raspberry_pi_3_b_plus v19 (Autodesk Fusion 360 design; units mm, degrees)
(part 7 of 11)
sketch "Sketch2" plane through (0, 0, 5.17) normal (0, 0, 1) x axis (-1, 0.0001, 0)
  line L1 (4.3404, -3.1995) -> (4.3405, -3.7995)
  line L2 (3.4404, -3.1996) -> (4.3404, -3.1995)
  line L3 (3.4405, -3.7996) -> (3.4404, -3.1996)
  line L4 (4.3405, -3.7995) -> (3.4405, -3.7996)
  line L5 (4.9405, -3.7994) -> (4.9404, -3.1994)
  line L6 (2.7854, -4.1591) -> (2.7354, -4.1591)
  line L7 (3.9604, -4.0652) -> (3.9604, -4.1092)
  line L8 (2.1854, -4.1591) -> (1.4604, -4.1591)
  line L9 (2.9747, -4.2244) -> (2.8668, -4.1763)
  line L10 (3.8604, -4.2092) -> (3.5269, -4.2092)
  line L11 (3.4504, -4.2244) -> (2.9747, -4.2244)
  line L12 (1.4604, -4.1591) -> (1.4604, -2.8397)
  line L13 (4.9404, -3.4994) -> (1.4604, -3.4994)
  line L14 (4.3405, -3.7995) -> (3.4405, -3.7996)
  line L15 (2.1854, -2.8397) -> (1.4604, -2.8397)
  line L16 (2.7854, -2.8397) -> (2.7354, -2.8397)
  line L17 (2.9747, -2.7744) -> (2.8668, -2.8224)
  line L18 (3.4504, -2.7744) -> (2.9747, -2.7744)
  line L19 (3.8604, -2.7896) -> (3.5269, -2.7896)
  line L20 (3.9604, -2.9336) -> (3.9604, -2.8896)
  line L21 (1.3604, -4.1323) -> (1.0901, -3.9762)
  line L22 (1.4604, -4.1591) -> (1.4604, -4.1591)
  line L23 (-2.17, -3.9494) -> (0.9901, -3.9494)
  line L24 (1.3604, -2.8665) -> (1.0901, -3.0226)
  line L25 (0.9901, -3.9494) -> (0.9901, -3.0494)
  line L26 (3.4405, -3.7996) -> (3.4404, -3.1996)
  line L27 (0.9604, -4.1591) -> (1.4604, -4.1591)
  line L28 (0.9604, -2.8353) -> (0.9604, -4.1591)
  line L29 (1.4604, -2.8397) -> (0.9604, -2.8353)
  arc A1 centre (3.5269, -4.4092) radius 0.2 clockwise from (3.4504, -4.2244) to (3.5269, -4.2092)
  arc A2 centre (4.2264, -3.6495) radius 0.15 clockwise from (4.2264, -3.7995) to (4.1434, -3.7744)
  arc A3 centre (4.0604, -3.8994) radius 0.15 clockwise from (3.9354, -3.9823) to (4.1434, -3.7744)
  arc A4 centre (3.8104, -4.0652) radius 0.15 clockwise from (3.9354, -3.9823) to (3.9604, -4.0652)
  arc A5 centre (3.8604, -4.1092) radius 0.1 clockwise from (3.9604, -4.1092) to (3.8604, -4.2092)
  arc A6 centre (2.7854, -4.3591) radius 0.2 clockwise from (2.7854, -4.1591) to (2.8668, -4.1763)
  arc A7 centre (2.7354, -4.3591) radius 0.2 clockwise from (2.5979, -4.2138) to (2.7354, -4.1591)
  arc A8 centre (2.4604, -4.0686) radius 0.2 clockwise from (2.5979, -4.2138) to (2.3229, -4.2138)
  arc A9 centre (2.1854, -4.3591) radius 0.2 clockwise from (2.1854, -4.1591) to (2.3229, -4.2138)
  arc A10 centre (2.1854, -2.6397) radius 0.2 clockwise from (2.3229, -2.785) to (2.1854, -2.8397)
  arc A11 centre (2.7354, -2.6397) radius 0.2 clockwise from (2.7354, -2.8397) to (2.5979, -2.785)
  arc A12 centre (2.7854, -2.6397) radius 0.2 clockwise from (2.8668, -2.8224) to (2.7854, -2.8397)
  arc A13 centre (3.5269, -2.5896) radius 0.2 clockwise from (3.5269, -2.7896) to (3.4504, -2.7744)
  arc A14 centre (3.8604, -2.8896) radius 0.1 clockwise from (3.8604, -2.7896) to (3.9604, -2.8896)
  arc A15 centre (3.8104, -2.9336) radius 0.15 clockwise from (3.9604, -2.9336) to (3.9354, -3.0165)
  arc A16 centre (4.0604, -3.0994) radius 0.15 clockwise from (4.1434, -3.2244) to (3.9354, -3.0165)
  arc A17 centre (4.2264, -3.3493) radius 0.15 clockwise from (4.1434, -3.2244) to (4.2264, -3.1993)
  arc A18 centre (2.4604, -2.9302) radius 0.2 clockwise from (2.3229, -2.785) to (2.5979, -2.785)
  arc A19 centre (1.4604, -3.9591) radius 0.2 clockwise from (1.4604, -4.1591) to (1.3604, -4.1323)
  arc A20 centre (0.9901, -4.1494) radius 0.2 clockwise from (0.9901, -3.9494) to (1.0901, -3.9762)
  arc A21 centre (0.9901, -2.8494) radius 0.2 clockwise from (1.0901, -3.0226) to (0.9901, -3.0494)
  arc A22 centre (1.4604, -3.0397) radius 0.2 clockwise from (1.3604, -2.8665) to (1.4604, -2.8397)
  point P32 (2.7604, -4.1591)
  point P35 (1.4604, -3.4994)
  point P33 (2.3229, -4.2138)
  point P37 (2.3229, -4.2138)
  point P36 (4.9404, -3.4994)
  point P22 (1.4604, -4.1591)
  point P38 (1.4604, -4.1591)
  point P9 (4.1434, -3.7744)
  point P62 (4.1434, -3.2244)
  point P10 (3.9604, -4.1092)
  point P57 (3.9604, -2.8896)
  point P12 (3.4504, -4.2244)
  point P52 (3.4504, -2.7744)
  point P13 (3.5269, -4.2092)
  point P54 (3.5269, -2.7896)
  point P14 (2.8668, -4.1763)
  point P50 (2.8668, -2.8224)
  point P16 (3.8604, -4.2092)
  point P55 (3.8604, -2.7896)
  point P17 (3.9354, -3.9823)
  point P60 (3.9354, -3.0165)
  point P18 (2.9747, -4.2244)
  point P51 (2.9747, -2.7744)
  point P19 (3.9604, -4.0652)
  point P58 (3.9604, -2.9336)
  point P20 (2.7854, -4.1591)
  point P48 (2.7854, -2.8397)
  point P21 (2.7354, -4.1591)
  point P46 (2.7354, -2.8397)
  point P41 (1.4604, -2.8397)
  point P23 (2.1854, -4.1591)
  point P42 (2.1854, -2.8397)
  point P29 (2.5979, -4.2138)
  point P47 (2.5979, -2.785)
  point P44 (2.3229, -2.785)
  point P66 (2.3229, -2.785)
  point P8 (1.4604, -2.8397)
  point P78 (1.4604, -2.8397)
  point P67 (1.3604, -4.1323)
  point P76 (1.3604, -2.8665)
  point P69 (0.9901, -3.9494)
  point P75 (0.9901, -3.0494)
  point P71 (1.0901, -3.9762)
  point P74 (1.0901, -3.0226)
  point P11 (4.2264, -3.7995)
  point P25 (4.0604, -3.8994)
  point P31 (2.4604, -4.0686)
  point P80 (0.9604, -4.1591)
  horizontal L8
  horizontal L11
  horizontal L10
  vertical L7
  vertical L12
  tangent A2 A3
  tangent A3 A4
  tangent L7 A4
  tangent L7 A5
  tangent A1 L10
  tangent L10 A5
  horizontal L6
  tangent L9 A6
  tangent L6 A6
  tangent L6 A7
  tangent A7 A8
  midpoint L6 P32
  tangent L8 A9
  collinear L6 L8
  midpoint L12 P35
  horizontal L13
  coincident P33 P37
  tangent A8 A9
  midpoint L5 P36
  tangent L4 A2
  coincident P22 P38
  symmetric P9 L13 P62
  symmetric P10 L13 P57
  symmetric P12 L13 P52
  symmetric P13 L13 P54
  symmetric P14 L13 P50
  symmetric P16 L13 P55
  symmetric P17 L13 P60
  symmetric P18 L13 P51
  symmetric P19 L13 P58
  symmetric P20 L13 P48
  symmetric P21 L13 P46
  symmetric P22 L13 P41
  symmetric P23 L13 P42
  symmetric A1 L13 A13
  symmetric A2 L13 A17
  symmetric A3 L13 A16
  symmetric A4 L13 A15
  symmetric A5 L13 A14
  symmetric A6 L13 A12
  symmetric P29 L13 P47
  symmetric A7 L13 A11
  symmetric A8 L13 A18
  symmetric P33 L13 P44
  symmetric A9 L13 A10
  symmetric L13 P37 P66
  coincident P8 P41
  perpendicular L12 L22
  tangent L8 A19
  horizontal L23
  tangent L21 A19
  tangent L21 A20
  equal A19 A20
  tangent L23 A20
  symmetric P22 L13 P78
  symmetric L13 P67 P76
  symmetric L13 A19 A22
  symmetric L13 P69 P75
  symmetric L13 P71 P74
  symmetric L13 A20 A21
  horizontal L27
  perpendicular L27 L28
  coincident L4 P11
  dimension "d304_1_1" = 0.15
  dimension "d305_1_1" radius A3 = 0.15
  dimension "d306_1_1" radius A4 = 0.15
  dimension "d307_1_1" radius A5 = 0.1
  dimension "d308_1_1" radius A1 = 0.2
  dimension "d309_1_1" angle L9 L11 = 24
  dimension "d310_1_1" distance L7 P32 = 1.2
  dimension "d311_1_1" radius A6 = 0.2
  dimension "d312_1_1" radius A7 = 0.2
  dimension "d313_1_1" radius A8 = 0.2
  dimension "d314_1_1" distance P20 P21 = 0.05
  dimension "d316_1_1" distance L8 L13 = 0.6597
  dimension "d317_1_1" distance P25 L13 = 0.4
  dimension "d319_1_1" distance L10 L13 = 0.7098
  dimension "d321_1_1" radius A9 = 0.2
  dimension "d323_1_1" distance L11 L13 = 0.725
  dimension "d326_1_1" distance P25 P36 = 0.88 (= "3.5 mm - 2.62 mm")
  dimension "d327_1_1" distance L7 P31 = 1.5
  dimension "d328_1_1" distance P10 P22 = 2.5
  dimension "d329_1_1" distance L7 P25 = 0.1
  dimension "d331_1_1" distance L13 L23 = 0.45
  dimension "d334_1_1" angle L13 L21 = 30
  dimension "d336_1_1" radius A19 = 0.2
  dimension "d370_1" distance P10 P12 = 0.51
  dimension "d372_1" distance P22 P80 = 0.5
extrude "Extrude1" cut sketch "Sketch2" profile of L2 L4 A2 A3 L14 A16 A17 against normal blind 0.45 named "d338_1_1"
extrude "Extrude2" add sketch "Sketch2" profile of L2 L4 L6 A1 L7 L8 L9 L10 L11 L12 A3 A4 A5 A6 A7 A8 A9 L14 L15 A10 A11 L16 A12 L17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 against normal blind 0.3 named "d340_1_1"
face "EdgeFlange3" FlangeHeight 0.43 named "d342_1_1" FlangeAngle 20 named "d343_1_1"
step "Unfold1"
extrude "Extrude3" cut sketch "Sketch2" profile of L21 A19 A20 A21 L24 A22 L25 L27 L28 L29 no distance stored
step "Refold1"
face "EdgeFlange4" FlangeHeight 5.5 named "d345_1_1" FlangeAngle 0 named "d346_1_1"
face "EdgeFlange5" FlangeHeight 1.5 named "d347_1_1" FlangeAngle 45 named "d348_1_1"
face "EdgeFlange6" FlangeHeight 0.4 named "d349_1_1" FlangeAngle 65 named "d350_1_1"
face "EdgeFlange7" FlangeHeight 1.25 named "d351_1_1" FlangeAngle 85 named "d352_1_1"
rectangular_pattern "R-Pattern4" uSpaceDistance -7 named "d375_1" vSpaceDistance 0 named "d376_1"
rectangular_pattern "R-Pattern5" uSpaceDistance -2.5 named "d379_2" vSpaceDistance 0 named "d380_2"
rectangular_pattern "R-Pattern6" uSpaceDistance -2 named "d383_1" vSpaceDistance 0 named "d384_1"
as_built_joint "As-built1"
sketch "Sketch1" plane through (0, 0, 0) normal (0, 0, 1) x axis (1, 0, 0)
  line L1 (-0.3175, -0.9525) -> (0.3175, -0.9525)
  line L2 (-0.3175, -1.5875) -> (-0.3175, -0.9525)
  line L3 (0.3175, -1.5875) -> (-0.3175, -1.5875)
  line L4 (0.3175, -0.9525) -> (0.3175, -1.5875)
  line L5 (-0.3175, -1.5875) -> (0.3175, -0.9525)
  line L6 (0.3175, -1.5875) -> (-0.3175, -0.9525)
  line L7 (0, -2.54) -> (0, 0)
  point P6 (0, -1.27)
  point P1 (0, 0)
  point P7 (0, 0)
  point P4 (-0.3175, -1.5875)
  point P5 (0.3175, -1.5875)
  point P3 (-0.3175, -0.9525)
  point P8 (0, -2.54)
  perpendicular L1 L2
  parallel L1 L3
  parallel L2 L4
  horizontal L1
  coincident L5 P6
  coincident L6 P6
  vertical P1 P6
  coincident P1 P7
  vertical L7
  dimension "d8_3" distance P4 P5 = 0.635 (= "h20x2_pin_size")
  dimension "d9_2" distance P3 P4 = 0.635 (= "h20x2_pin_size")
  dimension "d86_1" distance P1 P8 = 2.54 (= "h20x2_pins_deep * h20x2_spacing / 2")
  dimension "d88_1" distance P6 P8 = 1.27 (= "h20x2_spacing / 2")
extrude "Extrude1" new body sketch "Sketch1" profile of L1 L2 L3 L4 along normal blind 7 (= "h20x2_pin_height - h20x2_pin_descent") named "d10_1" and against normal blind 3 (= "h20x2_pin_descent") named "d12_1"
chamfer "Chamfer1" distance 0.1588 named "d13_3"
sketch "Sketch1" plane through (0, 0, 0) normal (0, 0, 1) x axis (1, 0, 0)
  line L1 (-1.27, -2.54) -> (49.53, -2.54)
  line L2 (-1.27, 2.54) -> (-1.27, -2.54)
  line L3 (49.53, 2.54) -> (-1.27, 2.54)
  line L4 (49.53, -2.54) -> (49.53, 2.54)
  line L5 (-1.27, 0) -> (0, 0)
  line L6 (0, 2.54) -> (0, 0)
  line L7 (-0.97, -2.5111) -> (-1.2247, -1.965)
  line L8 (0.97, -2.5111) -> (1.2247, -1.965)
  line L9 (-0.97, 2.5111) -> (-1.2247, 1.965)
  line L10 (0.97, 2.5111) -> (1.2247, 1.965)
  line L11 (1.57, 2.5111) -> (1.3153, 1.965)
  line L12 (3.51, 2.5111) -> (3.7647, 1.965)
  line L13 (3.51, -2.5111) -> (3.7647, -1.965)
  line L14 (1.57, -2.5111) -> (1.3153, -1.965)
  line L15 (4.11, 2.5111) -> (3.8553, 1.965)
  line L16 (6.05, 2.5111) -> (6.3047, 1.965)
  line L17 (6.05, -2.5111) -> (6.3047, -1.965)
  line L18 (4.11, -2.5111) -> (3.8553, -1.965)
  line L19 (6.65, 2.5111) -> (6.3953, 1.965)
  line L20 (8.59, 2.5111) -> (8.8447, 1.965)
  line L21 (8.59, -2.5111) -> (8.8447, -1.965)
  line L22 (6.65, -2.5111) -> (6.3953, -1.965)
  line L23 (9.19, 2.5111) -> (8.9353, 1.965)
  line L24 (11.13, 2.5111) -> (11.3847, 1.965)
  line L25 (11.13, -2.5111) -> (11.3847, -1.965)
  line L26 (9.19, -2.5111) -> (8.9353, -1.965)
  line L27 (11.73, 2.5111) -> (11.4753, 1.965)
  line L28 (13.67, 2.5111) -> (13.9247, 1.965)
  line L29 (13.67, -2.5111) -> (13.9247, -1.965)
  line L30 (11.73, -2.5111) -> (11.4753, -1.965)
  line L31 (14.27, 2.5111) -> (14.0153, 1.965)
  line L32 (16.21, 2.5111) -> (16.4647, 1.965)
  line L33 (16.21, -2.5111) -> (16.4647, -1.965)
  line L34 (14.27, -2.5111) -> (14.0153, -1.965)
  line L35 (16.81, 2.5111) -> (16.5553, 1.965)
  line L36 (18.75, 2.5111) -> (19.0047, 1.965)
  line L37 (18.75, -2.5111) -> (19.0047, -1.965)
  line L38 (16.81, -2.5111) -> (16.5553, -1.965)
  line L39 (19.35, 2.5111) -> (19.0953, 1.965)
  line L40 (21.29, 2.5111) -> (21.5447, 1.965)
  line L41 (21.29, -2.5111) -> (21.5447, -1.965)
  line L42 (19.35, -2.5111) -> (19.0953, -1.965)
  line L43 (21.89, 2.5111) -> (21.6353, 1.965)
  line L44 (23.83, 2.5111) -> (24.0847, 1.965)
  line L45 (23.83, -2.5111) -> (24.0847, -1.965)
  line L46 (21.89, -2.5111) -> (21.6353, -1.965)
  line L47 (24.43, 2.5111) -> (24.1753, 1.965)
  line L48 (26.37, 2.5111) -> (26.6247, 1.965)
  line L49 (26.37, -2.5111) -> (26.6247, -1.965)
  line L50 (24.43, -2.5111) -> (24.1753, -1.965)
  line L51 (26.97, 2.5111) -> (26.7153, 1.965)
  line L52 (28.91, 2.5111) -> (29.1647, 1.965)
  line L53 (28.91, -2.5111) -> (29.1647, -1.965)
  line L54 (26.97, -2.5111) -> (26.7153, -1.965)
  line L55 (29.51, 2.5111) -> (29.2553, 1.965)
  line L56 (31.45, 2.5111) -> (31.7047, 1.965)
  line L57 (31.45, -2.5111) -> (31.7047, -1.965)
  line L58 (29.51, -2.5111) -> (29.2553, -1.965)
  line L59 (32.05, 2.5111) -> (31.7953, 1.965)
  line L60 (33.99, 2.5111) -> (34.2447, 1.965)
  line L61 (33.99, -2.5111) -> (34.2447, -1.965)
  line L62 (32.05, -2.5111) -> (31.7953, -1.965)
  line L63 (34.59, 2.5111) -> (34.3353, 1.965)
  line L64 (36.53, 2.5111) -> (36.7847, 1.965)
  line L65 (36.53, -2.5111) -> (36.7847, -1.965)
  line L66 (34.59, -2.5111) -> (34.3353, -1.965)
  line L67 (37.13, 2.5111) -> (36.8753, 1.965)
  line L68 (39.07, 2.5111) -> (39.3247, 1.965)
  line L69 (39.07, -2.5111) -> (39.3247, -1.965)
  line L70 (37.13, -2.5111) -> (36.8753, -1.965)
  line L71 (39.67, 2.5111) -> (39.4153, 1.965)
  line L72 (41.61, 2.5111) -> (41.8647, 1.965)
  line L73 (41.61, -2.5111) -> (41.8647, -1.965)
  line L74 (39.67, -2.5111) -> (39.4153, -1.965)
  line L75 (42.21, 2.5111) -> (41.9553, 1.965)
  line L76 (44.15, 2.5111) -> (44.4047, 1.965)
  line L77 (44.15, -2.5111) -> (44.4047, -1.965)
  line L78 (42.21, -2.5111) -> (41.9553, -1.965)
  line L79 (44.75, 2.5111) -> (44.4953, 1.965)
  line L80 (46.69, 2.5111) -> (46.9447, 1.965)
  line L81 (46.69, -2.5111) -> (46.9447, -1.965)
  line L82 (44.75, -2.5111) -> (44.4953, -1.965)
  line L83 (47.29, 2.5111) -> (47.0353, 1.965)
  line L84 (49.23, 2.5111) -> (49.4847, 1.965)
  line L85 (49.23, -2.5111) -> (49.4847, -1.965)
  line L86 (47.29, -2.5111) -> (47.0353, -1.965)
  arc A1 centre (-0.9247, -2.49) radius 0.05 clockwise from (-0.9247, -2.54) to (-0.97, -2.5111)
  arc A2 centre (-1.27, -1.9861) radius 0.05 clockwise from (-1.27, -1.9361) to (-1.2247, -1.965)
  arc A3 centre (1.27, -1.9861) radius 0.05 clockwise from (1.2247, -1.965) to (1.27, -1.9361)
  arc A4 centre (0.9247, -2.49) radius 0.05 clockwise from (0.97, -2.5111) to (0.9247, -2.54)
  arc A5 centre (-1.27, 1.9861) radius 0.05 clockwise from (-1.2247, 1.965) to (-1.27, 1.9361)
  arc A6 centre (-0.9247, 2.49) radius 0.05 clockwise from (-0.97, 2.5111) to (-0.9247, 2.54)
  arc A7 centre (1.27, 1.9861) radius 0.05 clockwise from (1.27, 1.9361) to (1.2247, 1.965)
  arc A8 centre (0.9247, 2.49) radius 0.05 clockwise from (0.9247, 2.54) to (0.97, 2.5111)
  arc A9 centre (1.27, 1.9861) radius 0.05 clockwise from (1.3153, 1.965) to (1.27, 1.9361)
  arc A10 centre (1.6153, 2.49) radius 0.05 clockwise from (1.57, 2.5111) to (1.6153, 2.54)
  arc A11 centre (3.81, 1.9861) radius 0.05 clockwise from (3.81, 1.9361) to (3.7647, 1.965)
  arc A12 centre (3.4647, 2.49) radius 0.05 clockwise from (3.4647, 2.54) to (3.51, 2.5111)
  arc A13 centre (3.81, -1.9861) radius 0.05 clockwise from (3.7647, -1.965) to (3.81, -1.9361)
  arc A14 centre (3.4647, -2.49) radius 0.05 clockwise from (3.51, -2.5111) to (3.4647, -2.54)
  arc A15 centre (1.27, -1.9861) radius 0.05 clockwise from (1.27, -1.9361) to (1.3153, -1.965)
  arc A16 centre (1.6153, -2.49) radius 0.05 clockwise from (1.6153, -2.54) to (1.57, -2.5111)
  arc A17 centre (3.81, 1.9861) radius 0.05 clockwise from (3.8553, 1.965) to (3.81, 1.9361)
  arc A18 centre (4.1553, 2.49) radius 0.05 clockwise from (4.11, 2.5111) to (4.1553, 2.54)
  arc A19 centre (6.35, 1.9861) radius 0.05 clockwise from (6.35, 1.9361) to (6.3047, 1.965)
  arc A20 centre (6.0047, 2.49) radius 0.05 clockwise from (6.0047, 2.54) to (6.05, 2.5111)
  arc A21 centre (6.35, -1.9861) radius 0.05 clockwise from (6.3047, -1.965) to (6.35, -1.9361)
  arc A22 centre (6.0047, -2.49) radius 0.05 clockwise from (6.05, -2.5111) to (6.0047, -2.54)
  arc A23 centre (3.81, -1.9861) radius 0.05 clockwise from (3.81, -1.9361) to (3.8553, -1.965)
  arc A24 centre (4.1553, -2.49) radius 0.05 clockwise from (4.1553, -2.54) to (4.11, -2.5111)
  arc A25 centre (6.35, 1.9861) radius 0.05 clockwise from (6.3953, 1.965) to (6.35, 1.9361)
  arc A26 centre (6.6953, 2.49) radius 0.05 clockwise from (6.65, 2.5111) to (6.6953, 2.54)
  arc A27 centre (8.89, 1.9861) radius 0.05 clockwise from (8.89, 1.9361) to (8.8447, 1.965)
  arc A28 centre (8.5447, 2.49) radius 0.05 clockwise from (8.5447, 2.54) to (8.59, 2.5111)
  arc A29 centre (8.89, -1.9861) radius 0.05 clockwise from (8.8447, -1.965) to (8.89, -1.9361)
  arc A30 centre (8.5447, -2.49) radius 0.05 clockwise from (8.59, -2.5111) to (8.5447, -2.54)
  arc A31 centre (6.35, -1.9861) radius 0.05 clockwise from (6.35, -1.9361) to (6.3953, -1.965)
  arc A32 centre (6.6953, -2.49) radius 0.05 clockwise from (6.6953, -2.54) to (6.65, -2.5111)
  arc A33 centre (8.89, 1.9861) radius 0.05 clockwise from (8.9353, 1.965) to (8.89, 1.9361)
  arc A34 centre (9.2353, 2.49) radius 0.05 clockwise from (9.19, 2.5111) to (9.2353, 2.54)
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  point P1 (0, 0)
  point P6 (0, 0)
  point P7 (0, 0)
  point P9 (0, 0)
  point P13 (-0.9247, -2.54)
  point P15 (-1.27, -1.9361)
  point P16 (-1.27, -1.9861)
  point P11 (-1.2247, -1.965)
  point P18 (1.2247, -1.965)
  point P12 (-0.97, -2.5111)
  point P20 (0.97, -2.5111)
  point P22 (0.9247, -2.54)
  point P19 (1.27, -1.9361)
  point P24 (-1.2247, 1.965)
  point P27 (-0.97, 2.5111)
  point P28 (-0.9247, 2.54)
  point P25 (-1.27, 1.9361)
  point P31 (1.2247, 1.965)
  point P30 (1.27, 1.9361)
  point P34 (0.97, 2.5111)
  point P33 (0.9247, 2.54)
  point P8 (-1.27, 0)
  point P4 (-1.27, 2.54)
  point P5 (49.53, 2.54)
  point P3 (-1.27, -2.54)
  perpendicular L1 L2
  parallel L1 L3
  parallel L2 L4
  horizontal L1
  coincident P1 P6
  coincident P6 P7
  coincident P6 P9
  vertical L6
  horizontal L5
  coincident L1 P13
  tangent L7 A1
  coincident L2 P15
  tangent L7 A2
  equal A1 A2
  tangent L1 A1
  coincident L2 P16
  symmetric L6 P11 P18
  symmetric L6 P12 P20
  symmetric L6 P13 P22
  symmetric L6 A1 A4
  symmetric L6 P15 P19
  symmetric L6 A2 A3
  symmetric L5 P11 P24
  symmetric L5 P12 P27
  symmetric L5 P13 P28
  symmetric L5 A1 A6
  symmetric L5 P15 P25
  symmetric L5 A2 A5
  symmetric L5 P18 P31
  symmetric L5 P19 P30
  symmetric L5 A3 A7
  symmetric L5 P20 P34
  symmetric L5 P22 P33
  symmetric L5 A4 A8
  midpoint L2 P8
  dimension "d30_3" distance P4 P5 = 50.8 (= "h20x2_spacing * h20x2_pins_wide")
  dimension "d31_3" distance P3 P4 = 5.08 (= "h20x2_spacing * h20x2_pins_deep")
  dimension "d40_1" angle L2 L7 = 25 (= "h20x2_spacer_taper")
  dimension "d41_2" radius A1 = 0.05
  dimension "d42_2" distance L2 P12 = 0.3
  dimension "d63_2" distance L2 L6 = 1.27 (= "h20x2_spacing / 2")
  dimension "d66_1" R-Pattern1-uDistance = 2.54 (= "h20x2_spacing")
  dimension "d67_2" R-Pattern1-vDistance = 0
extrude "Extrude1" new body sketch "Sketch1" along normal blind 2.54 (= "h20x2_spacer_height") named "d43_1"
sketch "Sketch3" plane through (0, 0, 0) normal (0, 0, 1) x axis (1, 0, 0)
  line L1 (49.53, 2.04) -> (-1.27, 2.04)
  line L2 (49.53, -2.04) -> (49.53, 2.04)
  line L3 (-1.27, -2.04) -> (49.53, -2.04)
  line L4 (-1.27, 2.04) -> (-1.27, -2.04)
  line L5 (0, 0) -> (-1.27, 0)
  line L6 (-1.27, -2.54) -> (49.53, -2.54)
  point P6 (-1.27, 0)
  point P1 (0, 0)
  point P7 (0, 0)
  horizontal L1
  vertical L2
  horizontal L3
  vertical L4
  midpoint L4 P6
  coincident P1 P7
  perpendicular L4 L5
  dimension "d68_2" distance P1 L4 = 1.27 (= "h20x2_spacing / 2")
  dimension "d69_3" distance L2 L4 = 50.8 (= "h20x2_spacing * h20x2_pins_wide")
  dimension "d74_2" distance L3 L6 = 0.5 (= "h20x2_spacer_leg_size")
extrude "Extrude4" cut sketch "Sketch3" profile of L1 L2 L3 L4 along normal blind 0.5 (= "h20x2_spacer_leg_height") named "d72_2"
sketch "Sketch2" plane through (0, 0, 2.54) normal (0, 0, 1) x axis (-1, 0, 0)
  line L1 (-0.97, -2.5111) -> (-1.2247, -1.965)
  line L2 (1.2247, -1.965) -> (0.97, -2.5111)
  line L3 (1.27, 1.9361) -> (1.27, -1.9361)
  line L4 (0.97, 2.5111) -> (1.2247, 1.965)
  line L5 (-0.9247, 2.54) -> (0.9247, 2.54)
  line L6 (-1.2247, 1.965) -> (-0.97, 2.5111)
  line L7 (-49.53, -1.9361) -> (-49.53, 1.9361)
  line L8 (0.3175, 1.5875) -> (-0.3175, 1.5875)
  line L9 (0.3175, 0.9525) -> (0.3175, 1.5875)
  line L10 (-0.3175, 0.9525) -> (0.3175, 0.9525)
  line L11 (-0.3175, 1.5875) -> (-0.3175, 0.9525)
  line L12 (0.3175, 0.9525) -> (-0.3175, 1.5875)
  line L13 (-0.3175, 0.9525) -> (0.3175, 1.5875)
  line L14 (-1.57, 2.5111) -> (-1.3153, 1.965)
  line L15 (-3.4647, 2.54) -> (-1.6153, 2.54)
  line L16 (-3.7647, 1.965) -> (-3.51, 2.5111)
  line L17 (-4.11, 2.5111) -> (-3.8553, 1.965)
  line L18 (-6.0047, 2.54) -> (-4.1553, 2.54)
  line L19 (-6.3047, 1.965) -> (-6.05, 2.5111)
  line L20 (-6.65, 2.5111) -> (-6.3953, 1.965)
  line L21 (-8.5447, 2.54) -> (-6.6953, 2.54)
  line L22 (-8.8447, 1.965) -> (-8.59, 2.5111)
  line L23 (-9.19, 2.5111) -> (-8.9353, 1.965)
  line L24 (-11.0847, 2.54) -> (-9.2353, 2.54)
  line L25 (-11.3847, 1.965) -> (-11.13, 2.5111)
  line L26 (-11.73, 2.5111) -> (-11.4753, 1.965)
  line L27 (-13.6247, 2.54) -> (-11.7753, 2.54)
  line L28 (-13.9247, 1.965) -> (-13.67, 2.5111)
  line L29 (-14.27, 2.5111) -> (-14.0153, 1.965)
  line L30 (-16.1647, 2.54) -> (-14.3153, 2.54)
  line L31 (-16.4647, 1.965) -> (-16.21, 2.5111)
  line L32 (-16.81, 2.5111) -> (-16.5553, 1.965)
  line L33 (-18.7047, 2.54) -> (-16.8553, 2.54)
  line L34 (-19.0047, 1.965) -> (-18.75, 2.5111)
  line L35 (-19.35, 2.5111) -> (-19.0953, 1.965)
  line L36 (-21.2447, 2.54) -> (-19.3953, 2.54)
  line L37 (-21.5447, 1.965) -> (-21.29, 2.5111)
  line L38 (-21.89, 2.5111) -> (-21.6353, 1.965)
  line L39 (-23.7847, 2.54) -> (-21.9353, 2.54)
  line L40 (-24.0847, 1.965) -> (-23.83, 2.5111)
  line L41 (-24.43, 2.5111) -> (-24.1753, 1.965)
  line L42 (-26.3247, 2.54) -> (-24.4753, 2.54)
  line L43 (-26.6247, 1.965) -> (-26.37, 2.5111)
  line L44 (-26.97, 2.5111) -> (-26.7153, 1.965)
  line L45 (-28.8647, 2.54) -> (-27.0153, 2.54)
  line L46 (-29.1647, 1.965) -> (-28.91, 2.5111)
  line L47 (-29.51, 2.5111) -> (-29.2553, 1.965)
  line L48 (-31.4047, 2.54) -> (-29.5553, 2.54)
  line L49 (-31.7047, 1.965) -> (-31.45, 2.5111)
  line L50 (-32.05, 2.5111) -> (-31.7953, 1.965)
  line L51 (-33.9447, 2.54) -> (-32.0953, 2.54)
  line L52 (-34.2447, 1.965) -> (-33.99, 2.5111)
  line L53 (-34.59, 2.5111) -> (-34.3353, 1.965)
  line L54 (-36.4847, 2.54) -> (-34.6353, 2.54)
  line L55 (-36.7847, 1.965) -> (-36.53, 2.5111)
  line L56 (-37.13, 2.5111) -> (-36.8753, 1.965)
  line L57 (-39.0247, 2.54) -> (-37.1753, 2.54)
  line L58 (-39.3247, 1.965) -> (-39.07, 2.5111)
  line L59 (-39.67, 2.5111) -> (-39.4153, 1.965)
  line L60 (-41.5647, 2.54) -> (-39.7153, 2.54)
  line L61 (-41.8647, 1.965) -> (-41.61, 2.5111)
  line L62 (-42.21, 2.5111) -> (-41.9553, 1.965)
  line L63 (-44.1047, 2.54) -> (-42.2553, 2.54)
  line L64 (-44.4047, 1.965) -> (-44.15, 2.5111)
  line L65 (-44.75, 2.5111) -> (-44.4953, 1.965)
  line L66 (-46.6447, 2.54) -> (-44.7953, 2.54)
  line L67 (-46.9447, 1.965) -> (-46.69, 2.5111)
  line L68 (-47.29, 2.5111) -> (-47.0353, 1.965)
  line L69 (-49.1847, 2.54) -> (-47.3353, 2.54)
  line L70 (-49.4847, 1.965) -> (-49.23, 2.5111)
  line L71 (-49.23, -2.5111) -> (-49.4847, -1.965)
  line L72 (-47.3353, -2.54) -> (-49.1847, -2.54)
  line L73 (-47.0353, -1.965) -> (-47.29, -2.5111)
  line L74 (-46.69, -2.5111) -> (-46.9447, -1.965)
  line L75 (-44.7953, -2.54) -> (-46.6447, -2.54)
  line L76 (-44.4953, -1.965) -> (-44.75, -2.5111)
  line L77 (-44.15, -2.5111) -> (-44.4047, -1.965)
  line L78 (-42.2553, -2.54) -> (-44.1047, -2.54)
  line L79 (-41.9553, -1.965) -> (-42.21, -2.5111)
  line L80 (-41.61, -2.5111) -> (-41.8647, -1.965)
  line L81 (-39.7153, -2.54) -> (-41.5647, -2.54)
  line L82 (-39.4153, -1.965) -> (-39.67, -2.5111)
  line L83 (-39.07, -2.5111) -> (-39.3247, -1.965)
  line L84 (-37.1753, -2.54) -> (-39.0247, -2.54)
  line L85 (-36.8753, -1.965) -> (-37.13, -2.5111)
  line L86 (-36.53, -2.5111) -> (-36.7847, -1.965)
  line L87 (-34.6353, -2.54) -> (-36.4847, -2.54)
  line L88 (-34.3353, -1.965) -> (-34.59, -2.5111)
  line L89 (-33.99, -2.5111) -> (-34.2447, -1.965)
  line L90 (-32.0953, -2.54) -> (-33.9447, -2.54)
  line L91 (-31.7953, -1.965) -> (-32.05, -2.5111)
  line L92 (-31.45, -2.5111) -> (-31.7047, -1.965)
  line L93 (-29.5553, -2.54) -> (-31.4047, -2.54)
  line L94 (-29.2553, -1.965) -> (-29.51, -2.5111)
  line L95 (-28.91, -2.5111) -> (-29.1647, -1.965)
  line L96 (-27.0153, -2.54) -> (-28.8647, -2.54)
  line L97 (-26.7153, -1.965) -> (-26.97, -2.5111)
  line L98 (-26.37, -2.5111) -> (-26.6247, -1.965)
  line L99 (-24.4753, -2.54) -> (-26.3247, -2.54)
  line L100 (-24.1753, -1.965) -> (-24.43, -2.5111)
  line L101 (-23.83, -2.5111) -> (-24.0847, -1.965)
  line L102 (-21.9353, -2.54) -> (-23.7847, -2.54)
  line L103 (-21.6353, -1.965) -> (-21.89, -2.5111)
  line L104 (-21.29, -2.5111) -> (-21.5447, -1.965)
  line L105 (-19.3953, -2.54) -> (-21.2447, -2.54)
  line L106 (-19.0953, -1.965) -> (-19.35, -2.5111)
  line L107 (-18.75, -2.5111) -> (-19.0047, -1.965)
  line L108 (-16.8553, -2.54) -> (-18.7047, -2.54)
  line L109 (-16.5553, -1.965) -> (-16.81, -2.5111)
  line L110 (-16.21, -2.5111) -> (-16.4647, -1.965)
  line L111 (-14.3153, -2.54) -> (-16.1647, -2.54)
  line L112 (-14.0153, -1.965) -> (-14.27, -2.5111)
  line L113 (-13.67, -2.5111) -> (-13.9247, -1.965)
  line L114 (-11.7753, -2.54) -> (-13.6247, -2.54)
  line L115 (-11.4753, -1.965) -> (-11.73, -2.5111)
  line L116 (-11.13, -2.5111) -> (-11.3847, -1.965)
  line L117 (-9.2353, -2.54) -> (-11.0847, -2.54)
  line L118 (-8.9353, -1.965) -> (-9.19, -2.5111)
  line L119 (-8.59, -2.5111) -> (-8.8447, -1.965)
  line L120 (-6.6953, -2.54) -> (-8.5447, -2.54)
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  point P28 (0, 1.27)
  point P1 (0, 0)
  point P25 (0.3175, 1.5875)
  point P26 (0.3175, 0.9525)
  point P27 (-0.3175, 0.9525)
  perpendicular L8 L9
  parallel L8 L10
  parallel L9 L11
  horizontal L8
  coincident L12 P28
  coincident L13 P28
  vertical P1 P28
  dimension "d47_2" distance P25 P26 = 0.635 (= "h20x2_pin_size")
  dimension "d48_2" distance P26 P27 = 0.635 (= "h20x2_pin_size")
  dimension "d57_2" distance L5 P28 = 1.27 (= "h20x2_spacing / 2")
extrude "Extrude3" cut sketch "Sketch2" profile of L8 L9 L10 L11 no distance stored
rectangular_pattern "R-Pattern1" countU 2 (= "h20x2_pins_deep") named "d53_3" CountV 20 (= "h20x2_pins_wide") named "d54_3" uSpaceDistance 2.54 (= "h20x2_spacing") named "d55_2" vSpaceDistance 2.54 (= "h20x2_spacing") named "d56_2"
sketch "Sketch4" plane through (0, 0, 0) normal (0, 1, 0) x axis (1, 0, 0)
  line L1 (-1.27, -2.39) -> (-1.42, -2.54)
  line L2 (-1.12, -2.54) -> (-1.27, -2.39)
  line L3 (-1.42, -2.54) -> (-1.12, -2.54)
  line L4 (-1.27, -2.54) -> (-1.27, -2.39)
  point P5 (-1.27, -2.54)
  point P1 (0, 0)
  point P3 (-1.27, -2.39)
  horizontal L3
  midpoint L3 P5
  vertical L4
  perpendicular L1 L2
  dimension "d75_1" distance P1 L3 = 2.54 (= "h20x2_spacer_height")
  dimension "d76_2" distance P1 L4 = 1.27 (= "h20x2_spacing / 2")
  dimension "d77" distance P3 P5 = 0.15 (= "h20x2_spacer_break_depth")
extrude "Extrude5" cut sketch "Sketch4" profile of L1 L2 L3 no distance stored
rectangular_pattern "R-Pattern3" countU 21 (= "h20x2_pins_wide + 1") named "d80_1" uSpaceDistance 2.54 (= "h20x2_spacing") named "d82_2" vSpaceDistance 0 named "d83_2"
rectangular_pattern "R-Pattern1" countU 2 (= "h20x2_pins_deep") named "d89_2" CountV 20 (= "h20x2_pins_wide") named "d90_2" uSpaceDistance 2.54 (= "h20x2_spacing") named "d91_2" vSpaceDistance 2.54 (= "h20x2_spacing") named "d92_2"
position "Position1"
sketch "Sketch1" plane through (0, 0, 0) normal (0, 0, 1) x axis (1, 0, 0)
  line L1 (-0.3175, -0.9525) -> (0.3175, -0.9525)
  line L2 (-0.3175, -1.5875) -> (-0.3175, -0.9525)
  line L3 (0.3175, -1.5875) -> (-0.3175, -1.5875)
  line L4 (0.3175, -0.9525) -> (0.3175, -1.5875)
  line L5 (-0.3175, -1.5875) -> (0.3175, -0.9525)
  line L6 (0.3175, -1.5875) -> (-0.3175, -0.9525)
  line L7 (0, -2.54) -> (0, 0)
  point P6 (0, -1.27)
  point P1 (0, 0)
  point P7 (0, 0)
  point P4 (-0.3175, -1.5875)
  point P5 (0.3175, -1.5875)
  point P3 (-0.3175, -0.9525)
  point P8 (0, -2.54)
  perpendicular L1 L2
  parallel L1 L3
  parallel L2 L4
  horizontal L1
  coincident L5 P6
  coincident L6 P6
  vertical P1 P6
  coincident P1 P7
  vertical L7
  dimension "d8_7" distance P4 P5 = 0.635 (= "h2x2_pin_size")
  dimension "d9_3" distance P3 P4 = 0.635 (= "h2x2_pin_size")
  dimension "d86_4" distance P1 P8 = 2.54 (= "h2x2_pins_deep * h2x2_spacing / 2")
  dimension "d88_2" distance P6 P8 = 1.27 (= "h2x2_spacing / 2")
extrude "Extrude1" new body sketch "Sketch1" profile of L1 L2 L3 L4 along normal blind 7 (= "h2x2_pin_height - h2x2_pin_descent") named "d10_5" and against normal blind 3 (= "h2x2_pin_descent") named "d12_2"
chamfer "Chamfer1" distance 0.1588 named "d13_4"
sketch "Sketch1" plane through (0, 0, 0) normal (0, 0, 1) x axis (1, 0, 0)
  line L1 (-1.27, -2.54) -> (3.81, -2.54)
  line L2 (-1.27, 2.54) -> (-1.27, -2.54)
  line L3 (3.81, 2.54) -> (-1.27, 2.54)
  line L4 (3.81, -2.54) -> (3.81, 2.54)
  line L5 (-1.27, 0) -> (0, 0)
  line L6 (0, 2.54) -> (0, 0)
  line L7 (-0.97, -2.5111) -> (-1.2247, -1.965)
  line L8 (0.97, -2.5111) -> (1.2247, -1.965)
  line L9 (-0.97, 2.5111) -> (-1.2247, 1.965)
  line L10 (0.97, 2.5111) -> (1.2247, 1.965)
  line L11 (1.57, 2.5111) -> (1.3153, 1.965)
  line L12 (3.51, 2.5111) -> (3.7647, 1.965)
  line L13 (3.51, -2.5111) -> (3.7647, -1.965)
  line L14 (1.57, -2.5111) -> (1.3153, -1.965)
  arc A1 centre (-0.9247, -2.49) radius 0.05 clockwise from (-0.9247, -2.54) to (-0.97, -2.5111)
  arc A2 centre (-1.27, -1.9861) radius 0.05 clockwise from (-1.27, -1.9361) to (-1.2247, -1.965)
  arc A3 centre (1.27, -1.9861) radius 0.05 clockwise from (1.2247, -1.965) to (1.27, -1.9361)
  arc A4 centre (0.9247, -2.49) radius 0.05 clockwise from (0.97, -2.5111) to (0.9247, -2.54)
  arc A5 centre (-1.27, 1.9861) radius 0.05 clockwise from (-1.2247, 1.965) to (-1.27, 1.9361)
  arc A6 centre (-0.9247, 2.49) radius 0.05 clockwise from (-0.97, 2.5111) to (-0.9247, 2.54)
  arc A7 centre (1.27, 1.9861) radius 0.05 clockwise from (1.27, 1.9361) to (1.2247, 1.965)
  arc A8 centre (0.9247, 2.49) radius 0.05 clockwise from (0.9247, 2.54) to (0.97, 2.5111)
  arc A9 centre (1.27, 1.9861) radius 0.05 clockwise from (1.3153, 1.965) to (1.27, 1.9361)
  arc A10 centre (1.6153, 2.49) radius 0.05 clockwise from (1.57, 2.5111) to (1.6153, 2.54)
  arc A11 centre (3.81, 1.9861) radius 0.05 clockwise from (3.81, 1.9361) to (3.7647, 1.965)
  arc A12 centre (3.4647, 2.49) radius 0.05 clockwise from (3.4647, 2.54) to (3.51, 2.5111)
  arc A13 centre (3.81, -1.9861) radius 0.05 clockwise from (3.7647, -1.965) to (3.81, -1.9361)
  arc A14 centre (3.4647, -2.49) radius 0.05 clockwise from (3.51, -2.5111) to (3.4647, -2.54)
  arc A15 centre (1.27, -1.9861) radius 0.05 clockwise from (1.27, -1.9361) to (1.3153, -1.965)
  arc A16 centre (1.6153, -2.49) radius 0.05 clockwise from (1.6153, -2.54) to (1.57, -2.5111)
  point P1 (0, 0)
  point P6 (0, 0)
  point P7 (0, 0)
  point P9 (0, 0)
  point P13 (-0.9247, -2.54)
  point P15 (-1.27, -1.9361)
  point P16 (-1.27, -1.9861)
  point P11 (-1.2247, -1.965)
  point P18 (1.2247, -1.965)
  point P12 (-0.97, -2.5111)
  point P20 (0.97, -2.5111)
  point P22 (0.9247, -2.54)
  point P19 (1.27, -1.9361)
  point P24 (-1.2247, 1.965)
  point P27 (-0.97, 2.5111)
  point P28 (-0.9247, 2.54)
  point P25 (-1.27, 1.9361)
  point P31 (1.2247, 1.965)
  point P30 (1.27, 1.9361)
  point P34 (0.97, 2.5111)
  point P33 (0.9247, 2.54)
  point P8 (-1.27, 0)
  point P4 (-1.27, 2.54)
  point P5 (3.81, 2.54)
  point P3 (-1.27, -2.54)
  perpendicular L1 L2
  parallel L1 L3
  parallel L2 L4
  horizontal L1
  coincident P1 P6
  coincident P6 P7
  coincident P6 P9
  vertical L6
  horizontal L5
  coincident L1 P13
  tangent L7 A1
  coincident L2 P15
  tangent L7 A2
  equal A1 A2
  tangent L1 A1
  coincident L2 P16
  symmetric L6 P11 P18
  symmetric L6 P12 P20
  symmetric L6 P13 P22
  symmetric L6 A1 A4
  symmetric L6 P15 P19
  symmetric L6 A2 A3
  symmetric L5 P11 P24
  symmetric L5 P12 P27
  symmetric L5 P13 P28
  symmetric L5 A1 A6
  symmetric L5 P15 P25
  symmetric L5 A2 A5
  symmetric L5 P18 P31
  symmetric L5 P19 P30
  symmetric L5 A3 A7
  symmetric L5 P20 P34
  symmetric L5 P22 P33
  symmetric L5 A4 A8
  midpoint L2 P8
  dimension "d30_7" distance P4 P5 = 5.08 (= "h2x2_spacing * h2x2_pins_wide")
  dimension "d31_7" distance P3 P4 = 5.08 (= "h2x2_spacing * h2x2_pins_deep")
  dimension "d40_4" angle L2 L7 = 25 (= "h2x2_spacer_taper")
  dimension "d41_5" radius A1 = 0.05
  dimension "d42_5" distance L2 P12 = 0.3
  dimension "d63_5" distance L2 L6 = 1.27 (= "h2x2_spacing / 2")
  dimension "d66_4" R-Pattern1-uDistance = 2.54 (= "h2x2_spacing")
  dimension "d67_5" R-Pattern1-vDistance = 0
extrude "Extrude1" new body sketch "Sketch1" profile of L1 L2 L3 L4 L7 A1 A2 A3 L8 A4 A5 A6 L9 A7 A8 L10 A9 L11 A10 A11 A12 L12 A13 A14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 along normal blind 2.54 (= "h2x2_spacer_height") named "d43_4"
sketch "Sketch3" plane through (0, 0, 0) normal (0, 0, 1) x axis (1, 0, 0)
  line L1 (3.81, 2.04) -> (-1.27, 2.04)
  line L2 (3.81, -2.04) -> (3.81, 2.04)
  line L3 (-1.27, -2.04) -> (3.81, -2.04)
  line L4 (-1.27, 2.04) -> (-1.27, -2.04)
  line L5 (0, 0) -> (-1.27, 0)
  line L6 (-1.27, -2.54) -> (3.81, -2.54)
  point P6 (-1.27, 0)
  point P1 (0, 0)
  point P7 (0, 0)
  horizontal L1
  vertical L2
  horizontal L3
  vertical L4
  midpoint L4 P6
  coincident P1 P7
  perpendicular L4 L5
  dimension "d68_5" distance P1 L4 = 1.27 (= "h2x2_spacing / 2")
  dimension "d69_6" distance L2 L4 = 5.08 (= "h2x2_spacing * h2x2_pins_wide")
  dimension "d74_5" distance L3 L6 = 0.5 (= "h2x2_spacer_leg_size")
extrude "Extrude4" cut sketch "Sketch3" profile of L1 L2 L3 L4 along normal blind 0.5 (= "h2x2_spacer_leg_height") named "d72_3"
sketch "Sketch2" plane through (0, 0, 2.54) normal (0, 0, 1) x axis (-1, 0, 0)
  line L1 (-0.97, -2.5111) -> (-1.2247, -1.965)
  line L2 (0.9247, -2.54) -> (-0.9247, -2.54)
  line L3 (1.2247, -1.965) -> (0.97, -2.5111)
  line L4 (1.27, 1.9361) -> (1.27, -1.9361)
  line L5 (0.97, 2.5111) -> (1.2247, 1.965)
  line L6 (-0.9247, 2.54) -> (0.9247, 2.54)
  line L7 (-1.2247, 1.965) -> (-0.97, 2.5111)
  line L8 (-3.81, -1.9361) -> (-3.81, 1.9361)
  line L9 (0.3175, 1.5875) -> (-0.3175, 1.5875)
  line L10 (0.3175, 0.9525) -> (0.3175, 1.5875)
  line L11 (-0.3175, 0.9525) -> (0.3175, 0.9525)
  line L12 (-0.3175, 1.5875) -> (-0.3175, 0.9525)
  line L13 (0.3175, 0.9525) -> (-0.3175, 1.5875)
  line L14 (-0.3175, 0.9525) -> (0.3175, 1.5875)
  line L15 (-1.57, 2.5111) -> (-1.3153, 1.965)
  line L16 (-3.4647, 2.54) -> (-1.6153, 2.54)
  line L17 (-3.7647, 1.965) -> (-3.51, 2.5111)
  line L18
  line L19 (-1.6153, -2.54) -> (-3.4647, -2.54)
  line L20 (-1.3153, -1.965) -> (-1.57, -2.5111)
  arc A1 centre (-1.27, -1.9861) radius 0.05 clockwise from (-1.3153, -1.965) to (-1.2247, -1.965)
  arc A2 centre (-0.9247, -2.49) radius 0.05 clockwise from (-0.9247, -2.54) to (-0.97, -2.5111)
  arc A3 centre (0.9247, -2.49) radius 0.05 clockwise from (0.97, -2.5111) to (0.9247, -2.54)
  arc A4 centre (1.27, -1.9861) radius 0.05 clockwise from (1.2247, -1.965) to (1.27, -1.9361)
  arc A5 centre (1.27, 1.9861) radius 0.05 clockwise from (1.27, 1.9361) to (1.2247, 1.965)
  arc A6 centre (0.9247, 2.49) radius 0.05 clockwise from (0.9247, 2.54) to (0.97, 2.5111)
  arc A7 centre (-0.9247, 2.49) radius 0.05 clockwise from (-0.97, 2.5111) to (-0.9247, 2.54)
  arc A8 centre (-1.27, 1.9861) radius 0.05 clockwise from (-1.2247, 1.965) to (-1.3153, 1.965)
  arc A9 centre (-1.6153, 2.49) radius 0.05 clockwise from (-1.6153, 2.54) to (-1.57, 2.5111)
  arc A10 centre (-3.4647, 2.49) radius 0.05 clockwise from (-3.51, 2.5111) to (-3.4647, 2.54)
  arc A11 centre (-3.81, 1.9861) radius 0.05 clockwise from (-3.7647, 1.965) to (-3.81, 1.9361)
  arc A12 centre (-3.81, -1.9861) radius 0.05 clockwise from (-3.81, -1.9361) to (-3.7647, -1.965)
  arc A13 centre (-3.4647, -2.49) radius 0.05 clockwise from (-3.4647, -2.54) to (-3.51, -2.5111)
  arc A14 centre (-1.6153, -2.49) radius 0.05 clockwise from (-1.57, -2.5111) to (-1.6153, -2.54)
  point P30 (0, 1.27)
  point P1 (0, 0)
  point P27 (0.3175, 1.5875)
  point P28 (0.3175, 0.9525)
  point P29 (-0.3175, 0.9525)
  perpendicular L9 L10
  parallel L9 L11
  parallel L10 L12
  horizontal L9
  coincident L13 P30
  coincident L14 P30
  vertical P1 P30
  dimension "d47_3" distance P27 P28 = 0.635 (= "h2x2_pin_size")
  dimension "d48_5" distance P28 P29 = 0.635 (= "h2x2_pin_size")
  dimension "d57_5" distance L6 P30 = 1.27 (= "h2x2_spacing / 2")
extrude "Extrude3" cut sketch "Sketch2" profile of L9 L10 L11 L12 no distance stored
rectangular_pattern "R-Pattern1" countU 2 (= "h2x2_pins_deep") named "d53_6" CountV 2 (= "h2x2_pins_wide") named "d54_6" uSpaceDistance 2.54 (= "h2x2_spacing") named "d55_5" vSpaceDistance 2.54 (= "h2x2_spacing") named "d56_5"
sketch "Sketch4" plane through (0, 0, 0) normal (0, 1, 0) x axis (1, 0, 0)
  line L1 (-1.27, -2.39) -> (-1.42, -2.54)
  line L2 (-1.12, -2.54) -> (-1.27, -2.39)
  line L3 (-1.42, -2.54) -> (-1.12, -2.54)
  line L4 (-1.27, -2.54) -> (-1.27, -2.39)
  point P5 (-1.27, -2.54)
  point P1 (0, 0)
  point P3 (-1.27, -2.39)
  horizontal L3
  midpoint L3 P5
  vertical L4
  perpendicular L1 L2
  dimension "d75_4" distance P1 L3 = 2.54 (= "h2x2_spacer_height")
  dimension "d76_3" distance P1 L4 = 1.27 (= "h2x2_spacing / 2")
  dimension "d77_3" distance P3 P5 = 0.15 (= "h2x2_spacer_break_depth")
extrude "Extrude5" cut sketch "Sketch4" profile of L1 L2 L3 no distance stored
rectangular_pattern "R-Pattern3" countU 3 (= "h2x2_pins_wide + 1") named "d80_4" uSpaceDistance 2.54 (= "h2x2_spacing") named "d82_5" vSpaceDistance 0 named "d83_5"
rectangular_pattern "R-Pattern1" countU 2 (= "h2x2_pins_deep") named "d89_5" CountV 2 (= "h2x2_pins_wide") named "d90_3" uSpaceDistance 2.54 (= "h2x2_spacing") named "d91_5" vSpaceDistance 2.54 (= "h2x2_spacing") named "d92_5"
base_feature "Base Feature1"
copy_paste "CopyPaste2"
position "Position2"
base_feature "Base Feature1"
work_plane "WorkPlane1" AlongDistance 13.6 (= "13.5 mm + 0.1 mm") named "d2_5"
sketch "Sketch1" plane through (0, 0, 13.6) normal (0, 0, 1) x axis (1, 0, 0)
  line L1 (-7.65, -10.45) -> (7.65, -10.45)
  line L2 (-7.65, 10.3) -> (-7.65, -10.45)
  line L3 (7.65, 10.3) -> (-7.65, 10.3)
  line L4 (7.65, -10.45) -> (7.65, 10.3)
  line L5 (-7.65, 10.3) -> (7.65, -10.45)
  line L6 (7.65, 10.3) -> (-7.65, -10.45)
  point P6 (0, -0.075)
  point P1 (0, 0)
  point P4 (-7.65, 10.3)
  point P5 (7.65, 10.3)
  point P3 (-7.65, -10.45)
  perpendicular L1 L2
  parallel L1 L3
  parallel L2 L4
  horizontal L1
  coincident L5 P6
  coincident L6 P6
  vertical P1 P6
  dimension "d3_4" distance P4 P5 = 15.3 (= "15.9 mm - 4 * d1_5")
  dimension "d4_4" distance P3 P4 = 20.75 (= "21.35 mm - 4 * d1_5")
  dimension "d209_4" distance P1 L1 = 10.45 (= "10.75 mm - 2 * d1_5")
face "Face1" sketch "Sketch1"
face "EdgeFlange2" FlangeHeight 12.25 named "d5_2" FlangeAngle 90 named "d6_2"
face "EdgeFlange3" FlangeHeight 3 named "d7_4" FlangeAngle 90 named "d8_8" EdgeOffset_1 0 named "d27_5" EdgeOffset_2 -8.4 named "d28_5" BendRemnant 0.3 named "d29_5" EdgeOffset_1 -8.4 named "d39_4" EdgeOffset_2 0 named "d40_5"
face "EdgeFlange5" FlangeHeight 13.2 named "d16_5" FlangeAngle 90 named "d17_5"
face "EdgeFlange6" FlangeHeight 8.5 named "d18_7" FlangeAngle 90 named "d19_5"
face "EdgeFlange12" EdgeOffset_1 -0.65 named "d140_2" EdgeOffset_2 -0.65 named "d141_3" FlangeHeight 4 named "d142_1" FlangeAngle 90 named "d143_2" BendRemnant 0.3 named "d144_2"
step "Unfold1"
sketch "Sketch3" plane through (0, 0, 13.6) normal (0, 0, 1) x axis (-1, 0, 0)
  line L1 (7.65, 10.7893) -> (-7.65, 10.7893)
  line L2 (-7.65, 23.6893) -> (-7.01, 23.6893)
  line L3 (-7.65, 10.7893) -> (-7.65, 23.6893)
  line L4 (6.4, 12.7893) -> (6.4, 22.9893)
  line L5 (-6.4, 12.7893) -> (6.4, 12.7893)
  line L6 (-6.4, 22.9893) -> (-6.4, 12.7893)
  line L7 (6.4, 12.7893) -> (-6.4, 22.9893)
  line L8 (-6.4, 12.7893) -> (6.4, 22.9893)
  line L9 (0, 31.2963) -> (0, 0)
  line L10 (7.065, 20.7893) -> (6.4, 20.7893)
  line L11 (7.065, 22.9893) -> (7.065, 20.7893)
  line L12 (6.4, 22.9893) -> (7.065, 22.9893)
  line L13 (-7.065, 20.7893) -> (-6.4, 20.7893)
  line L14 (-7.065, 22.9893) -> (-7.065, 20.7893)
  line L15 (-6.4, 22.9893) -> (-7.065, 22.9893)
  line L16 (7.65, 23.6893) -> (7.65, 10.7893)
  line L17 (7.01, 23.6793) -> (7.01, 23.6893)
  line L18 (7, 23.6793) -> (7.01, 23.6793)
  line L19 (7, 23.6893) -> (7, 23.6793)
  line L20 (-7, 23.6893) -> (7, 23.6893)
  line L21 (-7, 23.6793) -> (-7, 23.6893)
  line L22 (-7.01, 23.6793) -> (-7, 23.6793)
  line L23 (-7.01, 23.6893) -> (-7.01, 23.6793)
  line L24 (7.01, 23.6893) -> (7.65, 23.6893)
  line L25 (2.5, 23.6893) -> (2.5, 22.9893)
  line L26 (-2.5, 23.6893) -> (-2.5, 22.9893)
  line L27 (-2.5, 22.9893) -> (-6.4, 22.9893)
  line L28 (6.4, 22.9893) -> (2.5, 22.9893)
  line L29 (-7, 24.0286) -> (7, 24.0286)
  line L30 (7, 24.0286) -> (-7, 24.0286)
  line L31 (2.5, 23.6893) -> (7, 23.6893)
  line L32 (-2.5, 23.6893) -> (-7, 23.6893)
  line L33 (-7.65, -10.6393) -> (7.65, -10.6393)
  line L34 (-7.65, -10.3) -> (7.65, -10.3)
  line L35 (6.15, -10.3) -> (6.15, -10.6393)
  line L36 (0.85, -10.3) -> (0.85, -10.6393)
  line L37 (-0.85, -10.3) -> (-0.85, -10.6393)
  line L38 (-6.15, -10.3) -> (-6.15, -10.6393)
  line L39 (-7.65, -10.6393) -> (-7.65, -10.3)
  line L40 (7.65, -10.3) -> (7.65, -10.6393)
  arc A1 centre (2.1607, 23.6893) radius 0.3393 clockwise from (2.1607, 24.0286) to (2.5, 23.6893)
  arc A2 centre (-2.1607, 23.6893) radius 0.3393 clockwise from (-2.5, 23.6893) to (-2.1607, 24.0286)
  point P10 (0, 17.8893)
  point P1 (0, 0)
  point P11 (0, 0)
  point P13 (6.4, 20.7893)
  point P7 (6.4, 22.9893)
  point P19 (-6.4, 22.9893)
  point P16 (-6.4, 20.7893)
  point P14 (7.065, 20.7893)
  point P17 (-7.065, 20.7893)
  point P15 (7.065, 22.9893)
  point P18 (-7.065, 22.9893)
  point P28 (2.5, 22.9893)
  point P29 (2.5, 23.6893)
  point P31 (-2.5, 23.6893)
  point P34 (-2.1607, 24.0286)
  point P32 (2.1607, 24.0286)
  point P24 (7, 23.6893)
  point P40 (7, 23.6893)
  point P25 (-7, 23.6893)
  point P41 (-7, 23.6893)
  point P46 (6.15, -10.6393)
  point P47 (6.15, -10.3)
  point P48 (0.85, -10.6393)
  point P49 (0.85, -10.3)
  point P50 (-0.85, -10.6393)
  point P51 (-0.85, -10.3)
  point P52 (-6.15, -10.6393)
  point P53 (-6.15, -10.3)
  point P8 (6.4, 12.7893)
  point P9 (-6.4, 12.7893)
  perpendicular L4 L27
  parallel L5 L27
  parallel L4 L6
  horizontal L27
  coincident L7 P10
  coincident L8 P10
  coincident P1 P11
  vertical L9
  coincident P10 L9
  coincident L4 P13
  perpendicular L4 L10
  perpendicular L10 L11
  horizontal L12
  symmetric P7 L9 P19
  symmetric L9 P13 P16
  symmetric L9 P14 P17
  symmetric L9 P15 P18
  coincident P28 L27
  coincident L20 P29
  coincident L20 P31
  vertical L26
  vertical L25
  symmetric L9 L25 L26
  collinear L27 L28
  tangent L25 A1
  coincident P34 L29
  tangent L26 A2
  tangent A2 L29
  tangent A1 L29
  coincident P32 L29
  coincident P24 P40
  coincident P25 P41
  coincident L33 P46
  coincident L34 P47
  perpendicular L34 L35
  coincident L33 P48
  coincident L34 P49
  perpendicular L34 L36
  coincident L33 P50
  coincident L34 P51
  perpendicular L34 L37
  coincident L33 P52
  coincident L34 P53
  perpendicular L34 L38
  symmetric L9 P49 P51
  symmetric L9 P47 P53
  dimension "d20_5" distance P8 P9 = 12.8
  dimension "d21_5" distance P7 P8 = 10.2
  dimension "d22_6" distance L1 L5 = 2
  dimension "d23_6" distance L10 L12 = 2.2
  dimension "d24_6" distance L11 L14 = 14.13
  dimension "d146_1" distance L25 L26 = 5
  dimension "d291_1" distance L36 L37 = 1.7
  dimension "d292_1" distance L38 L39 = 1.5
extrude "Extrude2" cut sketch "Sketch3" profile of L28 L4 L5 L6 L10 L11 L12 L13 L14 L15 no distance stored
extrude "Extrude7" cut sketch "Sketch3" profile of L33 L34 L35 L36 L37 L38 no distance stored
sketch "Sketch4" plane through (0, 0, 13.6) normal (0, 0, 1) x axis (-1, 0, 0)
  line L1 (-7.9893, 2.05) -> (-7.9893, -10.1939)
  line L2 (-10.8393, 2.05) -> (-7.9893, 2.05)
  line L3 (-10.8393, -7.3439) -> (-10.8393, 2.05)
  line L4 (-7.9893, -10.1939) -> (-10.8393, -7.3439)
  line L5 (-10.8393, -1.1393) -> (-7.65, 2.05)
  line L6 (7.9893, 2.05) -> (10.8393, 2.05)
  line L7 (10.8393, 2.05) -> (10.8393, -7.3439)
  line L8 (10.8393, -1.1393) -> (7.65, 2.05)
  line L9 (-7.9893, 2.05) -> (-7.65, 2.05)
  line L10 (7.65, 2.05) -> (7.9893, 2.05)
  point P7 (-10.8393, -1.1393)
  point P12 (10.8393, -1.1393)
  point P6 (-7.65, 2.05)
  point P13 (-7.65, 2.05)
  point P11 (7.65, 2.05)
  point P16 (7.65, 2.05)
  coincident L3 P7
  coincident L7 P12
  coincident P6 P13
  coincident P11 P16
  dimension "d30_8" angle L2 L5 = 45
  dimension "d41_6" angle L6 L8 = 45 (= "d30_8")
extrude "Extrude3" cut sketch "Sketch4" profile of L2 L3 L5 L6 L7 L8 no distance stored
